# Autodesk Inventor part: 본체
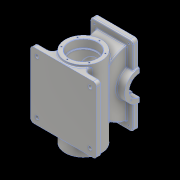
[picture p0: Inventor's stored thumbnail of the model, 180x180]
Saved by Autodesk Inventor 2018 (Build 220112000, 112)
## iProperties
Created: 2023-07
Part Number: 본체
Material: 알루미늄 6061
Document SubType Name: Modeling
Designer: home
Density: 2.7 g/cm^3
Appearance: 알루미늄 - 평지
Mass: 5727.18 g
Surface Area: 2841.69 cm^2
Volume: 2121.18 cm^3
Author: home
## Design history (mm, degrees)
sketch "스케치1"
  geometry: L1 (-90, 100)-(90, 100); L2 (100, 90)-(100, -90); L3 (90, -100)-(-90, -100); L4 (-100, -90)-(-100, 90); L5 (-100, 100)-(100, -100); L6 (100, 100)-(-100, -100); A1 r 10 centre (90, 90) between (100, 90) and (90, 100); A2 r 10 centre (90, -90) between (90, -100) and (100, -90); A3 r 10 centre (-90, -90) between (-100, -90) and (-90, -100); A4 r 10 centre (-90, 90) between (-90, 100) and (-100, 90); 1 further point
  constraints: 12 end point, 8 point on circle, 8 point on line, 8 tangent, 4 centre point, 3 equal radius, 2 midpoint, 2 parallel, 1 horizontal, 1 perpendicular
  dimensions: "d0" = 200 distance of L5.end L6.end; "d1" = 200 distance of L6.start L5.end; "d2" = 10 radius of A1
extrude "돌출1" new body sketch "스케치1" distance "d3" = 15; taper "d4" = 0 deg
sketch "스케치2"
  geometry: L1 (-90, 0)-(90, 0) reference; C1 r 55 at (0, 60); 1 further point
  constraints: 1 centre point
  dimensions: "d5" = 110 diameter of C1; "d6" = 60 distance from line of L1 C1.centre; "d7" = 108.16654 distance of L1.end C1.centre
extrude "돌출2" join sketch "스케치2" distance "d8" = 107; taper "d10" = 0 deg; dims "d9" = 135, "d11" = 0
node "작업 평면1"
sketch "스케치3"
  geometry: L1 (55, 120)-(-55, 120); L2 (-65, 110)-(-65, -110); L3 (-55, -120)-(55, -120); L4 (65, -110)-(65, 110); L5 (65, 120)-(-65, -120); L6 (-65, 120)-(65, -120); A1 r 10 centre (-55, 110) between (-55, 120) and (-65, 110); A2 r 10 centre (-55, -110) between (-65, -110) and (-55, -120); A3 r 10 centre (55, -110) between (55, -120) and (65, -110); A4 r 10 centre (55, 110) between (65, 110) and (55, 120); 1 further point
  constraints: 12 end point, 8 point on circle, 8 point on line, 8 tangent, 4 centre point, 3 equal radius, 2 midpoint, 2 parallel, 1 horizontal, 1 perpendicular
  dimensions: "d13" = 130 distance of L6.end L5.end; "d14" = 240 distance of L5.end L6.start; "d15" = 10 radius of A1 (derived)
extrude "돌출3" join sketch "스케치3" distance "d16" = 15; taper "d17" = 0 deg
sketch "스케치4"
  geometry: L1 (160, 110)-(160, -110) reference; L2 (160, -110)-(145, -110) reference; L3 (145, 110)-(145, -110) reference; L4 (160, 110)-(145, 110) reference; L5 (160, 100)-(160, -100); L6 (160, 110)-(160, -110) reference; A1 r 100 centre (160, 0) between (160, 100) and (160, -100); 1 further point
  constraints: 3 point on line, 2 end point, 2 point on circle, 1 centre point, 1 midpoint
  dimensions: "d18" = 100 radius of A1
extrude "돌출4" join sketch "스케치4" stored distance "d19" = 90; taper "d20" = 0 deg
sketch "스케치5"
  geometry: L1 (160, 110)-(160, -110) reference; L2 (160, -110)-(145, -110) reference; L3 (145, 110)-(145, -110) reference; L4 (160, 110)-(145, 110) reference; L5 (160, 110)-(160, -110) reference; L6 (160, 45)-(160, -45); A1 r 45 centre (160, 0) between (160, 45) and (160, -45); 1 further point
  constraints: 2 end point, 2 point on circle, 2 point on line, 1 centre point, 1 midpoint
  dimensions: "d21" = 45 radius of A1
extrude "돌출5" join sketch "스케치5" stored distance "d22" = 140; taper "d23" = 0 deg
sketch "스케치6"
  geometry: L1 (160, 45)-(160, -45) reference; L2 (160, 110)-(160, 45) reference; L3 (160, 87)-(160, -87); A1 r 87 centre (160, 0) between (160, 87) and (160, -87); 2 further points
  constraints: 2 end point, 2 midpoint, 2 point on circle, 1 centre point, 1 collinear, 1 horizontal alignment, 1 point on line
  dimensions: "d24" = 87 radius of A1
extrude "돌출6" cut sketch "스케치6" stored distance "d25" = 64; taper "d26" = 0 deg
hole "구멍1" diameter "d29" = 55; stored, may be unused: countersink angle "d33" = 90 deg, drill point angle "d35" = 0 deg; dims "d27" = 10, "d28" = 10, "d30" = 6, "d31" = 62, "d32" = 23, "d34" = 50
sketch "스케치7"
  geometry: L1 (-31, 160)-(-45, 160) reference; L2 (45, 160)-(31, 160) reference; A1 r 31 centre (0, 160) between (-31, 160) and (31, 160) reference; A2 r 45 centre (0, 160) between (-45, 160) and (45, 160) reference; 2 further points
  dimensions: "d38" = 26.16295 distance from line of point (26.163, 133.837) L1; "d39" = 32.23871 distance of L2.start point (26.163, 133.837)
hole "구멍2" sketch "스케치7" at (26.163, 133.837) diameter "d40" = 4.134; stored, may be unused: countersink angle "d44" = 90 deg, drill point angle "d46" = 118 deg; dims "d41" = 10, "d42" = 62, "d43" = 23, "d45" = 12
hole "구멍3" diameter "d52" = 77; stored, may be unused: countersink angle "d56" = 90 deg, drill point angle "d58" = 0 deg; dims "d53" = 10, "d54" = 85, "d55" = 25, "d57" = 242, "d114" = 10, "d115" = 10
hole "구멍4" diameter "d61" = 85; stored, may be unused: countersink angle "d65" = 90 deg, drill point angle "d67" = 0 deg; dims "d59" = 10, "d60" = 10, "d62" = 10, "d63" = 85, "d64" = 25, "d66" = 25
sketch "스케치8"
  geometry: C1 r 42.5 at (0, 0) reference; C2 r 55 at (0, 0) reference; C3 r 55 at (0, 0) reference; 2 further points
  dimensions: "d71" = 48.5 distance of C1.centre point (0, 48.5); "d72" = 108.5 distance of point (0, -60) point (0, 48.5)
hole "구멍5" sketch "스케치8" at (0, 48.5) diameter "d73" = 4.134; stored, may be unused: countersink angle "d77" = 90 deg, drill point angle "d79" = 118 deg; dims "d74" = 10, "d75" = 85, "d76" = 25, "d78" = 12
sketch "스케치9"
  geometry: C1 r 42.5 at (0, 0) reference; C2 r 55 at (0, 0) reference; 2 further points
  dimensions: "d84" = 48.5 distance of C1.centre point (0, 48.5); "d85" = 108.5 distance of point (0, -60) point (0, 48.5)
hole "구멍6" sketch "스케치9" at (0, 48.5) diameter "d86" = 4.134; stored, may be unused: countersink angle "d90" = 90 deg, drill point angle "d92" = 118 deg; dims "d87" = 10, "d88" = 85, "d89" = 25, "d91" = 12
sketch "스케치10"
  geometry: L1 (-100, -90)-(-100, 90) reference; L2 (-90, 100)-(90, 100) reference; L3 (100, 90)-(100, -90) reference; L4 (90, -100)-(-90, -100) reference; L5 (-100, 0)-(100, 0); L6 (-90, 100)-(90, 100) reference; L7 (0, 100)-(0, -100); L8 (31.623, -100)-(-31.623, -100) reference; A1 r 10 centre (-90, 90) between (-90, 100) and (-100, 90) reference; A2 r 10 centre (90, 90) between (100, 90) and (90, 100) reference; A3 r 10 centre (90, -90) between (90, -100) and (100, -90) reference; A4 r 10 centre (-90, -90) between (-100, -90) and (-90, -100) reference; 5 further points
  constraints: 4 end point, 4 midpoint, 2 horizontal alignment, 2 vertical alignment
  dimensions: "d96" = 160 distance of point (80, -80) point (-80, -80); "d97" = 160 distance of point (80, 80) point (80, -80); "d98" = 80 distance from line of point (80, -80) L5; "d99" = 80 distance from line of point (-80, -80) L7
hole "구멍7" sketch "스케치10" at (-80, 80), (80, 80), (80, -80), (-80, -80) diameter "d100" = 11; stored, may be unused: countersink angle "d104" = 90 deg, drill point angle "d106" = 0 deg; dims "d101" = 10, "d102" = 28, "d103" = 2, "d105" = 15
fillet "모깎기1" dims "d107" = 1.1
fillet "모깎기2" dims "d108" = 15
fillet "모깎기3" dims "d109" = 3
fillet "모깎기4" dims "d110" = 3
fillet "모깎기5" dims "d111" = 3
fillet "모깎기6" dims "d112" = 1
fillet "모깎기7" dims "d113" = 3
fillet "모깎기8" dims "d116" = 3
sketch "스케치11"
  geometry: L1 (-55, 120)-(55, 120) reference; L2 (55, -120)-(-55, -120) reference; L3 (65, -48)-(65, -110) reference; L4 (-65, -110)-(-65, -48) reference; L5 (-65, 48)-(-65, 110) reference; L6 (65, 110)-(65, 48) reference; 5 further points
  constraints: 2 horizontal alignment, 2 vertical alignment
  dimensions: "d117" = 104 distance of point (-52, 107) point (52, 107); "d118" = 214 distance of point (-52, -107) point (-52, 107); "d119" = 52 horizontal distance of point (0, 0) point (52, 107); "d120" = 107 vertical distance of point (0, 0) point (-52, 107)
hole "구멍8" sketch "스케치11" at (-52, 107), (52, -107), (-52, -107), (52, 107) diameter "d121" = 4.917; stored, may be unused: countersink angle "d125" = 90 deg, drill point angle "d127" = 0 deg; dims "d122" = 15, "d123" = 28, "d124" = 2, "d126" = 15
sketch "스케치12"
  geometry: L1 (100, -90)-(100, 90) reference; 2 further points
  constraints: 1 horizontal alignment, 1 other
  dimensions: "d128" = 15 distance from line of L1 point (85, 0)
feature "엠보싱1" sketch "스케치12" dims "d0" = 200, "d1" = 200, "d2" = 10, "d7" = 108.16654, "d129" = 0.5, "d130" = 0
chamfer "모따기1" distance "d131" = 1; stored, may be unused: second distance "d132" = 2, angle "d133" = 45 deg
node "솔리드1"
pattern_circular "원형 패턴1" dims angle "d48" = -90 deg
mirror "미러1"
pattern_circular "원형 패턴2" dims angle "d81" = 360 deg
pattern_circular "원형 패턴3" dims angle "d94" = 360 deg
node "투영된 루프1"
node "투영된 루프2"
node "투영된 루프3"
node "투영된 루프4"
node "투영된 루프5"
node "투영된 루프6"
